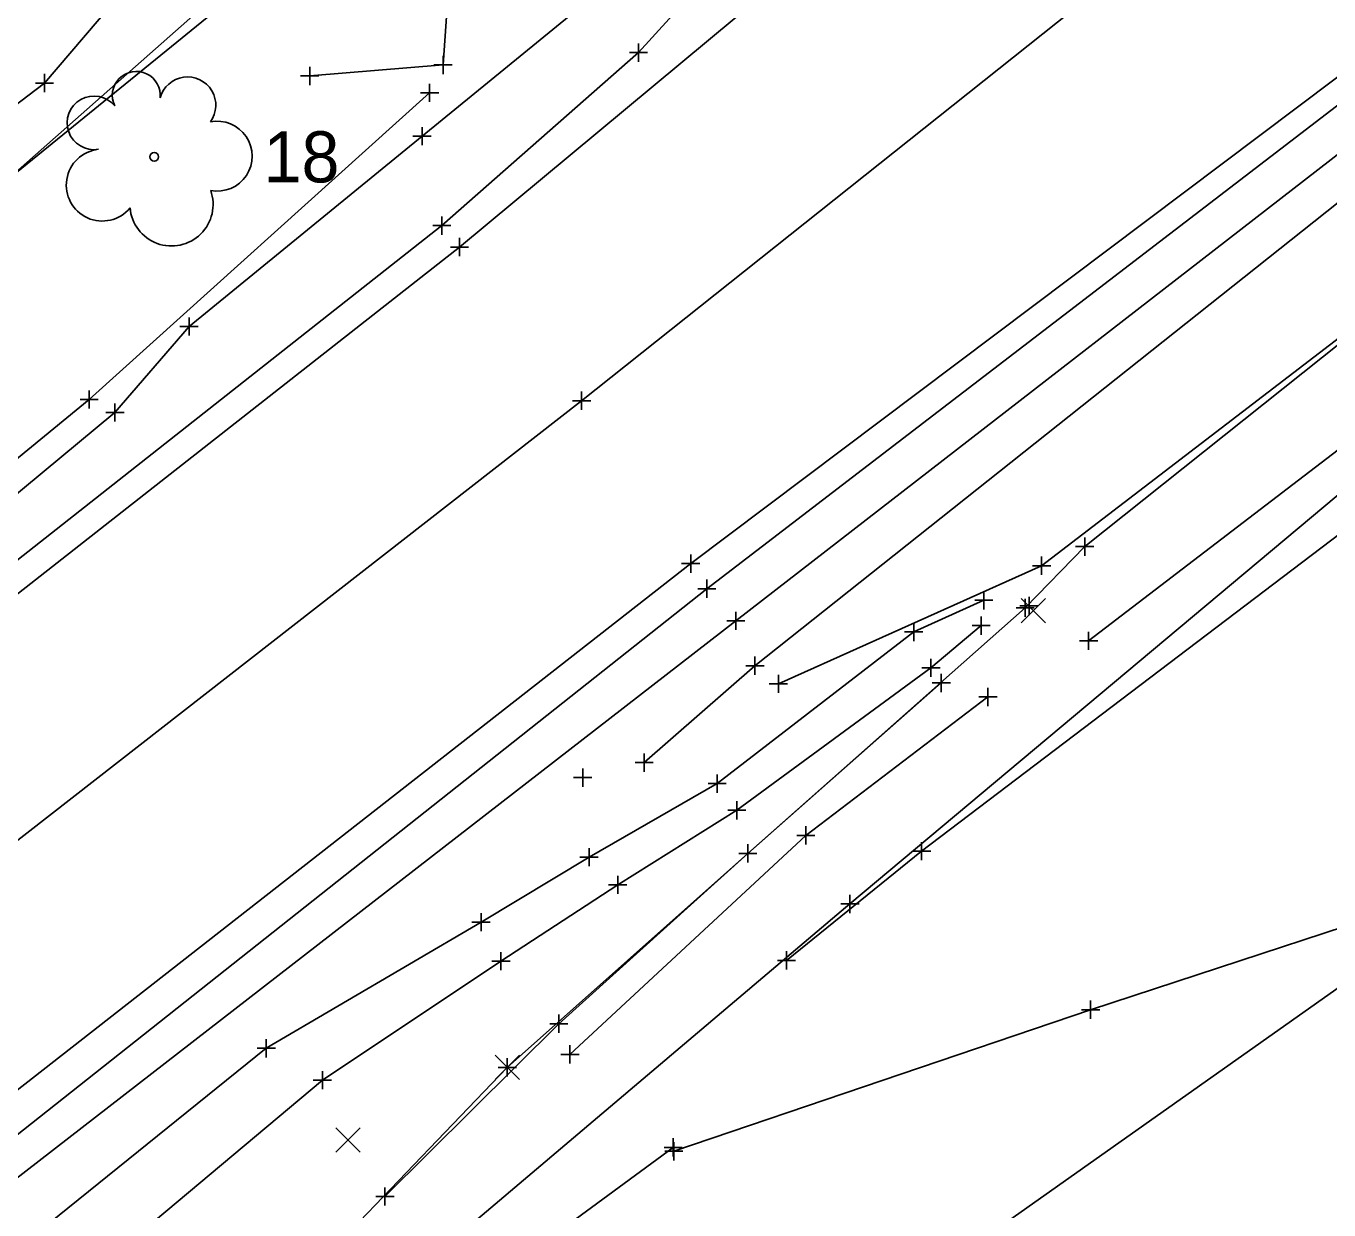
# Model space of a CAD drawing. Extents: x 2184635 to 2185378, y 369880 to 370486.
# Drawn here: x 2184953 to 2185024.5, y 370120.8 to 370185.8 of the extents above; entities that cross this region are included whole.
import ezdxf

# ---------------------------------------------------------------- set-up
doc = ezdxf.new("R2010")
doc.units = 0
for name, color, linetype in [('_CIVIL_CONSTRUCTION', 7, 'Continuous'), ('GE_X_Alignment', 7, 'Continuous'), ('GE_X_Alignment_100_Distances', 7, 'Continuous'), ('PM_X_CL_Pass_Proh_Lt', 7, 'Continuous'), ('PM_X_CL_Pass_Proh_Rt', 7, 'Continuous'), ('PM_X_Edge_Line', 7, 'Continuous'), ('PV_X_COP', 7, 'Continuous'), ('PV_X_EOP', 7, 'Continuous'), ('PV_X_Shoulder', 7, 'Continuous'), ('RD_X_Fence', 7, 'Continuous'), ('RD_X_GR_Rt', 7, 'Continuous'), ('RW_X_CL', 7, 'Continuous'), ('SV_X_Break_Lines', 7, 'Continuous'), ('SV_X_Terrain_Boundary', 7, 'Continuous'), ('SV_X_Top_of_Bank', 7, 'Continuous'), ('UT_X_Gas', 7, 'Continuous'), ('VG_X_Text', 7, 'Continuous'), ('VG_X_Tree_Line_Lt', 7, 'Continuous')]:
    doc.layers.add(name, color=color, linetype=linetype)

msp = doc.modelspace()

# ---------------------------------------------------------------- linework, layer by layer
at = {"layer": '_CIVIL_CONSTRUCTION'}
for p, q in [((2185007.614, 370153.033), (2185008.948, 370154.368)), ((2185007.614, 370154.368), (2185008.948, 370153.033)), ((2184978.74, 370127.973), (2184980.073, 370129.308)), ((2184978.74, 370129.308), (2184980.073, 370127.973)), ((2184970.003, 370123.981), (2184971.336, 370125.316)), ((2184970.003, 370125.316), (2184971.336, 370123.981))]:
    msp.add_line(p, q, dxfattribs=at)
at = {"layer": 'GE_X_Alignment'}
msp.add_circle((2184960.028, 370178.589), 0.24, dxfattribs=at)
for centre, radius, start, end in [((2184959.044, 370181.956), 1.317, 354.0047, 205.97412), ((2184961.854, 370181.418), 1.553, 323.82996, 165.0376), ((2184956.719, 370180.453), 1.471, 39.06254, 279.54124), ((2184963.488, 370178.625), 1.915, 259.14531, 101.45961), ((2184957.175, 370177.04), 1.974, 96.17219, 320.57371), ((2184960.974, 370175.984), 2.284, 184.94757, 19.45715)]:
    msp.add_arc(centre, radius, start, end, dxfattribs=at)
at = {"layer": 'GE_X_Alignment_100_Distances'}
for points in [[(2185264.317, 370371.308), (2185225.669, 370339.838), (2185186.917, 370307.744), (2185148.745, 370277.089), (2185109.073, 370245.724), (2185070.468, 370214.753), (2185031.044, 370183.419), (2184991.951, 370153.137), (2184952.243, 370122.384), (2184912.885, 370091.687), (2184876.597, 370062.99), (2184874.528, 370062.204), (2184872.479, 370060.466), (2184871.454, 370058.823), (2184869.46, 370057.791), (2184834.83, 370028.947), (2184796.151, 369998.173), (2184773.728, 369979.618), (2184757.686, 369965.832), (2184717.275, 369935.855), (2184678.357, 369904.181)], [(2184659.612, 369925.949), (2184700.373, 369957.788), (2184738.497, 369988.629), (2184777.827, 370020.252), (2184816.427, 370051.346), (2184855.546, 370082.582), (2184897.005, 370115.363), (2184935.605, 370145.229), (2184944.916, 370153.839), (2184957.869, 370164.566), (2184961.936, 370169.284), (2184974.725, 370179.722), (2184983.893, 370187.218), (2184992.505, 370194.662), (2184997.566, 370200.246)]]:
    msp.add_lwpolyline(points, dxfattribs=at)
at = {"layer": 'PM_X_CL_Pass_Proh_Lt'}
msp.add_lwpolyline([(2185262.142, 370374.202), (2185223.699, 370342.03), (2185185.178, 370310.659), (2185146.677, 370279.544), (2185107.738, 370248.35), (2185068.5, 370216.963), (2185029.051, 370186.04), (2184989.472, 370156.275), (2184949.89, 370125.369), (2184910.765, 370094.563), (2184870.979, 370063.529), (2184832.077, 370032.401), (2184793.204, 370001.486), (2184754.34, 369970.024), (2184715.121, 369938.505), (2184676.144, 369907.221)], dxfattribs=at)
at = {"layer": 'PM_X_CL_Pass_Proh_Rt'}
msp.add_lwpolyline([(2184772.075, 369998.33), (2184786.357, 370009.443), (2184824.962, 370040.257), (2184864.241, 370071.885), (2184905.968, 370104.805), (2184943.399, 370133.995), (2184983.483, 370165.213), (2185020.257, 370194.467), (2185061.224, 370226.635), (2185099.743, 370257.779), (2185139.182, 370289.511), (2185177.352, 370320.307), (2185216.054, 370351.804), (2185254.728, 370383.452)], dxfattribs=at)
at = {"layer": 'PM_X_Edge_Line'}
msp.add_lwpolyline([(2184661.525, 369922.948), (2184702.122, 369955.424), (2184740.459, 369986.306), (2184779.792, 370018.036), (2184818.421, 370048.832), (2184857.458, 370080.192), (2184899.139, 370112.801), (2184937.357, 370142.735), (2184976.78, 370173.64), (2185013.226, 370203.926), (2185054.743, 370235.213), (2185093.131, 370266.204), (2185132.902, 370298.208), (2185170.876, 370328.987), (2185209.713, 370360.437), (2185248.243, 370392.049)], dxfattribs=at)
at = {"layer": 'PV_X_COP'}
msp.add_lwpolyline([(2184667.936, 369914.544), (2184708.437, 369946.755), (2184746.444, 369977.522), (2184786.357, 370009.443), (2184824.962, 370040.257), (2184864.241, 370071.885), (2184905.968, 370104.805), (2184943.399, 370133.995), (2184983.483, 370165.213), (2185020.257, 370194.467), (2185061.224, 370226.635), (2185099.743, 370257.779), (2185139.182, 370289.511), (2185177.352, 370320.307), (2185216.054, 370351.804), (2185254.679, 370383.196)], dxfattribs=at)
at = {"layer": 'PV_X_EOP'}
for points in [[(2184661.562, 369922.858), (2184702.122, 369955.424), (2184740.459, 369986.306), (2184779.792, 370018.036), (2184818.421, 370048.832), (2184857.458, 370080.192), (2184899.139, 370112.801), (2184937.357, 370142.735), (2184976.78, 370173.64), (2185013.226, 370203.926), (2185054.743, 370235.213), (2185093.131, 370266.204), (2185132.902, 370298.208), (2185170.876, 370328.987), (2185209.713, 370360.437), (2185248.181, 370392.045)], [(2185262.152, 370374.256), (2185223.699, 370342.03), (2185185.178, 370310.659), (2185146.677, 370279.544), (2185107.738, 370248.35), (2185068.5, 370216.963), (2185029.051, 370186.04), (2184989.472, 370156.275), (2184949.89, 370125.369), (2184910.765, 370094.563), (2184870.979, 370063.529), (2184832.077, 370032.401), (2184793.204, 370001.486), (2184754.34, 369970.024), (2184715.121, 369938.505), (2184676.223, 369907.131)]]:
    msp.add_lwpolyline(points, dxfattribs=at)
at = {"layer": 'PV_X_Shoulder'}
for points in [[(2184660.616, 369924.653), (2184701.177, 369956.993), (2184739.308, 369987.689), (2184778.66, 370019.08), (2184817.145, 370050.202), (2184856.424, 370081.402), (2184897.962, 370114.276), (2184936.317, 370143.726), (2184975.811, 370174.815), (2184986.608, 370184.308), (2184994.082, 370192.548), (2185011.043, 370206.648), (2185033.171, 370224.287), (2185051.814, 370238.9), (2185062.885, 370246.964), (2185064.956, 370248.001), (2185067.328, 370248.113), (2185092.06, 370267.243), (2185132.002, 370299.513), (2185169.971, 370330.255), (2185208.837, 370361.607), (2185247.242, 370392.983)], [(2185263.127, 370373.08), (2185224.626, 370341.08), (2185185.979, 370309.587), (2185147.251, 370278.484), (2185108.316, 370247.412), (2185069.303, 370216.141), (2185029.865, 370185.151), (2184990.36, 370154.899), (2184951.083, 370123.826), (2184911.784, 370093.315), (2184872.077, 370062.156), (2184833.336, 370030.958), (2184794.18, 369999.967), (2184755.603, 369968.652), (2184716.02, 369937.324), (2184677.487, 369905.633)]]:
    msp.add_lwpolyline(points, dxfattribs=at)
at = {"layer": 'RD_X_Fence'}
for points in [[(2184974.137, 370097.077), (2184970.447, 370119.306), (2184979.406, 370128.641), (2184992.607, 370140.381), (2185007.827, 370153.847), (2185011.099, 370157.209), (2185036.107, 370177.129), (2185063.41, 370198.922), (2185078.716, 370210.935), (2185113.226, 370240.316), (2185152.641, 370271.084), (2185187.441, 370299.506), (2185189.075, 370300.14), (2185213.006, 370319.114), (2185230.361, 370333.854), (2185268.576, 370364.897)], [(2185015.199, 370283.15), (2185015.458, 370270.123), (2185015.389, 370244.361), (2185014.511, 370228.509), (2185000.874, 370217.983), (2184983.945, 370203.779), (2184965.468, 370188.326), (2184938.367, 370166.286), (2184905.933, 370138.502), (2184906.07, 370146.446), (2184906.533, 370163.609)]]:
    msp.add_lwpolyline(points, dxfattribs=at)
at = {"layer": 'RD_X_GR_Rt'}
msp.add_lwpolyline([(2184986.918, 370145.362), (2184992.997, 370150.672), (2185032.04, 370181.661), (2185071.402, 370212.899), (2185110.342, 370243.768), (2185149.195, 370274.959), (2185188, 370305.912), (2185226.97, 370337.52), (2185265.615, 370369.567), (2185308.993, 370405.417), (2185377.709, 370462.246)], dxfattribs=at)
at = {"layer": 'RW_X_CL'}
for p, q in [((2184986.608, 370184.808), (2184986.608, 370183.808)), ((2184975.878, 370184.129), (2184975.878, 370183.129)), ((2184986.108, 370184.308), (2184987.108, 370184.308)), ((2184986.608, 370184.308), (2184986.608, 370184.308)), ((2184954.002, 370183.136), (2184954.002, 370182.136)), ((2184968.562, 370183.524), (2184968.562, 370182.524)), ((2184975.378, 370183.629), (2184976.378, 370183.629)), ((2184975.878, 370183.629), (2184975.878, 370183.629)), ((2184953.502, 370182.636), (2184954.502, 370182.636)), ((2184954.002, 370182.636), (2184954.002, 370182.636)), ((2184968.062, 370183.024), (2184969.062, 370183.024)), ((2184968.562, 370183.024), (2184968.562, 370183.024)), ((2184975.144, 370182.601), (2184975.144, 370181.601)), ((2184974.644, 370182.101), (2184975.644, 370182.101)), ((2184975.144, 370182.101), (2184975.144, 370182.101)), ((2184974.725, 370180.222), (2184974.725, 370179.222)), ((2184974.225, 370179.722), (2184975.225, 370179.722)), ((2184974.725, 370179.722), (2184974.725, 370179.722)), ((2184975.811, 370175.315), (2184975.811, 370174.315)), ((2184975.311, 370174.815), (2184976.311, 370174.815)), ((2184975.811, 370174.815), (2184975.811, 370174.815)), ((2184976.78, 370174.14), (2184976.78, 370173.14)), ((2184976.78, 370174.14), (2184976.78, 370173.14)), ((2184976.28, 370173.64), (2184977.28, 370173.64)), ((2184976.28, 370173.64), (2184977.28, 370173.64)), ((2184976.78, 370173.64), (2184976.78, 370173.64)), ((2184976.78, 370173.64), (2184976.78, 370173.64)), ((2184961.936, 370169.784), (2184961.936, 370168.784)), ((2184961.436, 370169.284), (2184962.436, 370169.284)), ((2184961.936, 370169.284), (2184961.936, 370169.284)), ((2184955.954, 370165.28), (2184956.954, 370165.28)), ((2184956.454, 370165.78), (2184956.454, 370164.78)), ((2184956.454, 370165.28), (2184956.454, 370165.28)), ((2184982.983, 370165.213), (2184983.983, 370165.213)), ((2184982.983, 370165.213), (2184983.983, 370165.213)), ((2184983.483, 370165.713), (2184983.483, 370164.713)), ((2184983.483, 370165.713), (2184983.483, 370164.713)), ((2184983.483, 370165.213), (2184983.483, 370165.213)), ((2184983.483, 370165.213), (2184983.483, 370165.213)), ((2184957.369, 370164.566), (2184958.369, 370164.566)), ((2184957.869, 370165.066), (2184957.869, 370164.066)), ((2184957.869, 370164.566), (2184957.869, 370164.566)), ((2185011.099, 370157.709), (2185011.099, 370156.709)), ((2184989.472, 370156.775), (2184989.472, 370155.775)), ((2184989.472, 370156.775), (2184989.472, 370155.775)), ((2185008.734, 370156.661), (2185008.734, 370155.661)), ((2185010.599, 370157.209), (2185011.599, 370157.209)), ((2185011.099, 370157.209), (2185011.099, 370157.209)), ((2184988.972, 370156.275), (2184989.972, 370156.275)), ((2184988.972, 370156.275), (2184989.972, 370156.275)), ((2184989.472, 370156.275), (2184989.472, 370156.275)), ((2184989.472, 370156.275), (2184989.472, 370156.275)), ((2185008.234, 370156.161), (2185009.234, 370156.161)), ((2185008.734, 370156.161), (2185008.734, 370156.161)), ((2184990.36, 370155.399), (2184990.36, 370154.399)), ((2184989.86, 370154.899), (2184990.86, 370154.899)), ((2184990.36, 370154.899), (2184990.36, 370154.899)), ((2185005.564, 370154.766), (2185005.564, 370153.766)), ((2185008.04, 370154.456), (2185008.04, 370153.456)), ((2185005.064, 370154.266), (2185006.064, 370154.266)), ((2185005.564, 370154.266), (2185005.564, 370154.266)), ((2185007.327, 370153.847), (2185008.327, 370153.847)), ((2185007.54, 370153.956), (2185008.54, 370153.956)), ((2185007.827, 370154.347), (2185007.827, 370153.347)), ((2185007.827, 370153.847), (2185007.827, 370153.847)), ((2185008.04, 370153.956), (2185008.04, 370153.956)), ((2184991.451, 370153.137), (2184992.451, 370153.137)), ((2184991.951, 370153.637), (2184991.951, 370152.637)), ((2184991.951, 370153.137), (2184991.951, 370153.137)), ((2185001.713, 370153.025), (2185001.713, 370152.025)), ((2185005.414, 370153.372), (2185005.414, 370152.372)), ((2185001.213, 370152.525), (2185002.213, 370152.525)), ((2185001.713, 370152.525), (2185001.713, 370152.525)), ((2185004.914, 370152.872), (2185005.914, 370152.872)), ((2185005.414, 370152.872), (2185005.414, 370152.872)), ((2185011.314, 370152.537), (2185011.314, 370151.537)), ((2185010.814, 370152.037), (2185011.814, 370152.037)), ((2185011.314, 370152.037), (2185011.314, 370152.037)), ((2184992.997, 370151.172), (2184992.997, 370150.172)), ((2185002.661, 370151.06), (2185002.661, 370150.06)), ((2184992.497, 370150.672), (2184993.497, 370150.672)), ((2184992.997, 370150.672), (2184992.997, 370150.672)), ((2184994.285, 370150.18), (2184994.285, 370149.18)), ((2185002.161, 370150.56), (2185003.161, 370150.56)), ((2185002.661, 370150.56), (2185002.661, 370150.56)), ((2185003.227, 370150.227), (2185003.227, 370149.227)), ((2184993.785, 370149.68), (2184994.785, 370149.68)), ((2184994.285, 370149.68), (2184994.285, 370149.68)), ((2185002.727, 370149.727), (2185003.727, 370149.727)), ((2185003.227, 370149.727), (2185003.227, 370149.727)), ((2185005.789, 370149.463), (2185005.789, 370148.463)), ((2185005.289, 370148.963), (2185006.289, 370148.963)), ((2185005.789, 370148.963), (2185005.789, 370148.963)), ((2184986.918, 370145.862), (2184986.918, 370144.862)), ((2184986.418, 370145.362), (2184987.418, 370145.362)), ((2184986.918, 370145.362), (2184986.918, 370145.362)), ((2184983.048, 370144.537), (2184984.048, 370144.537)), ((2184983.548, 370145.037), (2184983.548, 370144.037)), ((2184983.548, 370144.537), (2184983.548, 370144.537)), ((2184990.927, 370144.707), (2184990.927, 370143.707)), ((2184990.427, 370144.207), (2184991.427, 370144.207)), ((2184990.927, 370144.207), (2184990.927, 370144.207)), ((2184992.006, 370143.246), (2184992.006, 370142.246)), ((2184991.506, 370142.746), (2184992.506, 370142.746)), ((2184992.006, 370142.746), (2184992.006, 370142.746)), ((2184995.793, 370141.865), (2184995.793, 370140.865)), ((2184992.607, 370140.881), (2184992.607, 370139.881)), ((2184992.607, 370140.881), (2184992.607, 370139.881)), ((2184995.293, 370141.365), (2184996.293, 370141.365)), ((2184995.793, 370141.365), (2184995.793, 370141.365)), ((2185002.148, 370141.002), (2185002.148, 370140.002)), ((2184983.394, 370140.174), (2184984.394, 370140.174)), ((2184983.894, 370140.674), (2184983.894, 370139.674)), ((2184983.894, 370140.174), (2184983.894, 370140.174)), ((2184992.107, 370140.381), (2184993.107, 370140.381)), ((2184992.107, 370140.381), (2184993.107, 370140.381)), ((2184992.607, 370140.381), (2184992.607, 370140.381)), ((2184992.607, 370140.381), (2184992.607, 370140.381)), ((2185001.648, 370140.502), (2185002.648, 370140.502)), ((2185002.148, 370140.502), (2185002.148, 370140.502)), ((2184985.468, 370139.155), (2184985.468, 370138.155)), ((2184984.968, 370138.655), (2184985.968, 370138.655)), ((2184985.468, 370138.655), (2184985.468, 370138.655)), ((2184998.214, 370138.106), (2184998.214, 370137.106)), ((2184997.714, 370137.606), (2184998.714, 370137.606)), ((2184998.214, 370137.606), (2184998.214, 370137.606)), ((2184977.464, 370136.606), (2184978.464, 370136.606)), ((2184977.964, 370137.106), (2184977.964, 370136.106)), ((2184977.964, 370136.606), (2184977.964, 370136.606)), ((2184978.56, 370134.464), (2184979.56, 370134.464)), ((2184979.06, 370134.964), (2184979.06, 370133.964)), ((2184979.06, 370134.464), (2184979.06, 370134.464)), ((2184994.232, 370134.509), (2184995.232, 370134.509)), ((2184994.732, 370135.009), (2184994.732, 370134.009)), ((2184994.732, 370134.509), (2184994.732, 370134.509)), ((2185011.422, 370132.3), (2185011.422, 370131.3)), ((2185010.922, 370131.8), (2185011.922, 370131.8)), ((2185011.422, 370131.8), (2185011.422, 370131.8)), ((2184981.737, 370131.038), (2184982.737, 370131.038)), ((2184982.237, 370131.538), (2184982.237, 370130.538)), ((2184982.237, 370131.038), (2184982.237, 370131.038)), ((2184966.175, 370130.187), (2184966.175, 370129.187)), ((2184965.675, 370129.687), (2184966.675, 370129.687)), ((2184966.175, 370129.687), (2184966.175, 370129.687)), ((2184982.844, 370129.854), (2184982.844, 370128.854)), ((2184979.406, 370129.141), (2184979.406, 370128.141)), ((2184982.344, 370129.354), (2184983.344, 370129.354)), ((2184982.844, 370129.354), (2184982.844, 370129.354)), ((2184969.257, 370128.438), (2184969.257, 370127.438)), ((2184978.906, 370128.641), (2184979.906, 370128.641)), ((2184979.406, 370128.641), (2184979.406, 370128.641)), ((2184968.757, 370127.938), (2184969.757, 370127.938)), ((2184969.257, 370127.938), (2184969.257, 370127.938)), ((2184988.511, 370124.748), (2184988.511, 370123.748)), ((2184988.546, 370124.541), (2184988.546, 370123.541)), ((2184988.011, 370124.248), (2184989.011, 370124.248)), ((2184988.046, 370124.041), (2184989.046, 370124.041)), ((2184988.511, 370124.248), (2184988.511, 370124.248)), ((2184988.546, 370124.041), (2184988.546, 370124.041)), ((2184972.188, 370121.56), (2184973.188, 370121.56)), ((2184972.688, 370122.06), (2184972.688, 370121.06)), ((2184972.688, 370121.56), (2184972.688, 370121.56))]:
    msp.add_line(p, q, dxfattribs=at)
at = {"layer": 'SV_X_Break_Lines'}
for points in [[(2185266.896, 370366.662), (2185229.269, 370335.467), (2185210.515, 370320.131), (2185189.044, 370300.271), (2185187.441, 370299.506), (2185152.641, 370271.084), (2185113.226, 370240.316), (2185078.716, 370210.935), (2185063.41, 370198.922), (2185036.107, 370177.129), (2185008.734, 370156.161), (2184994.285, 370149.68)], [(2185011.314, 370152.037), (2185029.522, 370165.964), (2185043.39, 370177.165), (2185060.22, 370191.124), (2185082.453, 370208.384), (2185104.298, 370224.36), (2185119.101, 370237.21), (2185133.03, 370247.825), (2185147.963, 370260.154)], [(2184981.838, 370244.628), (2184966.756, 370227.412), (2184963.344, 370214.869), (2184959.896, 370189.547), (2184954.002, 370182.636), (2184940.542, 370172.414), (2184922.269, 370158.192)], [(2184968.562, 370183.024), (2184975.878, 370183.629), (2184976.495, 370192.379), (2184976.779, 370197.149), (2184984.923, 370205.689), (2184989.467, 370217.083), (2184991.273, 370229.49), (2184994.097, 370239.432)], [(2184994.732, 370134.509), (2185002.148, 370140.502), (2185025.645, 370158.329), (2185030.88, 370163.109), (2185037.291, 370164.77), (2185039.415, 370170.503)], [(2184877.551, 370059.028), (2184884.763, 370064.482), (2184895.426, 370072.136), (2184903.712, 370080.01), (2184915.313, 370089.034), (2184927.655, 370099.056), (2184938.515, 370107.685), (2184946.67, 370114.52), (2184954.238, 370120.081), (2184966.175, 370129.687), (2184977.964, 370136.606), (2184983.894, 370140.174), (2184990.927, 370144.207), (2185001.713, 370152.525), (2185005.564, 370154.266)], [(2184881.037, 370056.635), (2184887.302, 370061.16), (2184897.496, 370068.719), (2184906.263, 370076.899), (2184917.263, 370086.354), (2184930.975, 370096.702), (2184941.021, 370105.171), (2184949.47, 370110.555), (2184956.364, 370117.136), (2184969.257, 370127.938), (2184979.06, 370134.464), (2184985.468, 370138.655), (2184992.006, 370142.746), (2185002.661, 370150.56), (2185005.414, 370152.872)], [(2185005.789, 370148.963), (2184995.793, 370141.365), (2184982.844, 370129.354)], [(2184977.477, 370116.141), (2184988.511, 370124.248), (2184988.546, 370124.041), (2185011.422, 370131.8), (2185033.603, 370139.079)]]:
    msp.add_lwpolyline(points, dxfattribs=at)
at = {"layer": 'SV_X_Terrain_Boundary'}
msp.add_lwpolyline([(2184636.069, 369950.037), (2184651.151, 369938.985), (2184701.215, 369883.063), (2184720.068, 369902.68), (2184776.086, 369948.877), (2184881.346, 369949.865), (2184898.748, 369959.788), (2184956.333, 369996.082), (2184974.539, 370008.088), (2184974.137, 370097.077), (2185033.603, 370139.079)], dxfattribs=at)
at = {"layer": 'SV_X_Top_of_Bank'}
for points in [[(2184975.144, 370182.101), (2184956.454, 370165.28), (2184940.406, 370152.123), (2184932.657, 370144.859), (2184909.734, 370127.354)], [(2184972.688, 370121.56), (2184982.237, 370131.038), (2184992.607, 370140.381), (2185003.227, 370149.727)]]:
    msp.add_lwpolyline(points, dxfattribs=at)
at = {"layer": 'UT_X_Gas'}
msp.add_lwpolyline([(2184953.242, 370098.442), (2184967.159, 370111.339), (2184998.214, 370137.606), (2185039.424, 370172.123), (2185069.412, 370195.978), (2185086.695, 370210.093), (2185109.697, 370228.178), (2185131.189, 370247.901), (2185147.466, 370264.362), (2185212.955, 370317.623), (2185242.558, 370341.915), (2185269.196, 370362.683)], dxfattribs=at)
at = {"layer": 'VG_X_Tree_Line_Lt'}
msp.add_lwpolyline([(2185010.677, 370261.152), (2185009.496, 370230.83), (2184994.447, 370214.873), (2184919.447, 370148.63), (2184883.31, 370122.364), (2184845.078, 370084.673), (2184789.476, 370110.598), (2184762.675, 370135.815)], dxfattribs=at)

# ---------------------------------------------------------------- texts
at = {"layer": 'VG_X_Text'}
msp.add_text('18', height=2.8, dxfattribs=at).set_placement((2184966.028, 370177.189))

doc.saveas('drawing.dxf')
